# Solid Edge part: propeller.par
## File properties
Author: Georg
Template: Iso Metric Part.par
Last saved by: Georg
Revision: 7
Application: Solid Edge
Accuracy: 0,990
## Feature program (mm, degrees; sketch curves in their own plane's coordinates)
sketch for "unnamed RevolvedProtrusion 1" plane through (0, 0, 0) normal (1, 0, 0) x-axis (0, 1, 0)
  line (0, -121.0602) -> (-276.8667, -121.0602)
  line (0, -121.0602) -> (0, -271.0602)
revolve "unnamed RevolvedProtrusion 1" add finite 360 deg
lofted protrusion "unnamed LoftedProtrusion 1"
fillet "Round_1" radius 3.4154
pattern "unnamed Pattern 1" of "unnamed LoftedProtrusion 1"
lofted protrusion "unnamed LoftedProtrusion 2"
lofted protrusion "unnamed LoftedProtrusion 3"
sketch for "ExtrudedProtrusion_1" plane through (0, 0, -121.0602) normal (0, 1, 0) x-axis (-1, 0, 0)
  circle centre (0, 0) radius 15
extrude "ExtrudedProtrusion_1" add finite 170 along +normal
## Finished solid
Body 1: solid body, 29 faces, 93 edges, 68 vertices.
  Faces by surface: spline 12, plane 11, blend 4, cylinder 1, spun 1
  Edges by curve: intersection 40, circle 21, line 20, spline 12
Bounding box of the edges (mm; curved faces can reach further): 1087.408 x 276.360 x 941.723, from (-543.7038, -106.36, -441.7227) to (543.7038, 170, 500).
Cylindrical faces by radius (mm): R15 x1
Planar faces by outward normal: +y 2, +z 1, -z 2, oblique 6
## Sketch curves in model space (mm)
line (7.1074, -21.7531, 500) -> (11.6999, -26.3455, 500)
line (11.6999, -26.3455, 500) -> (-7.1074, -45.1528, 500)
line (-7.1074, -45.1528, 500) -> (-11.6999, -40.5604, 500)
line (-11.6999, -40.5604, 500) -> (7.1074, -21.7531, 500)
arc centre (65.8364, 27.9899, 250) radius 10 from (72.9075, 20.9188, 250) through (75.8322, 28.2807, 250) to (72.9075, 35.0609, 250)
line (72.9075, 35.0609, 250) -> (68.5138, 39.4546, 250)
arc centre (61.4428, 32.3835, 250) radius 10 from (68.5138, 39.4546, 250) through (61.1519, 42.3793, 250) to (54.3717, 39.4546, 250)
line (54.3717, 39.4546, 250) -> (-72.9075, -87.8246, 250)
arc centre (-65.8364, -94.8957, 250) radius 10 from (-72.9075, -87.8246, 250) through (-75.8322, -95.1865, 250) to (-72.9075, -101.9668, 250)
line (-72.9075, -101.9668, 250) -> (-68.5138, -106.3604, 250)
arc centre (-61.4428, -99.2894, 250) radius 10 from (-54.3717, -106.3604, 250) through (-61.7336, -109.2851, 250) to (-68.5138, -106.3604, 250)
line (-54.3717, -106.3604, 250) -> (72.9075, 20.9188, 250)
arc centre (78.034, -30.3461, 0) radius 10 from (78.034, -20.3461, 0) through (85.3077, -23.4837, 0) to (88.034, -30.3461, 0)
line (88.034, -30.3461, 0) -> (88.034, -36.5597, 0)
arc centre (78.034, -36.5597, 0) radius 10 from (88.034, -36.5597, 0) through (84.8964, -43.8334, 0) to (78.034, -46.5597, 0)
line (78.034, -46.5597, 0) -> (-78.034, -46.5597, 0)
arc centre (-78.034, -36.5597, 0) radius 10 from (-78.034, -46.5597, 0) through (-85.3077, -43.4221, 0) to (-88.034, -36.5597, 0)
line (-88.034, -36.5597, 0) -> (-88.034, -30.3461, 0)
arc centre (-78.034, -30.3461, 0) radius 10 from (-78.034, -20.3461, 0) through (-85.3077, -23.4837, 0) to (-88.034, -30.3461, 0)
line (-78.034, -20.3461, 0) -> (78.034, -20.3461, 0)
ellipse centre (0, 0, -121.0602) radii 276.8667, 150 from (0, -276.8667, -121.0602) through (0, -189.9974, -230.1662) to (0, 0, -271.0602)
line (0, 0, -121.0602) -> (0, -276.8667, -121.0602)
line (0, 0, -121.0602) -> (0, 0, -271.0602)
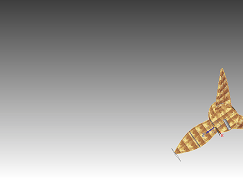
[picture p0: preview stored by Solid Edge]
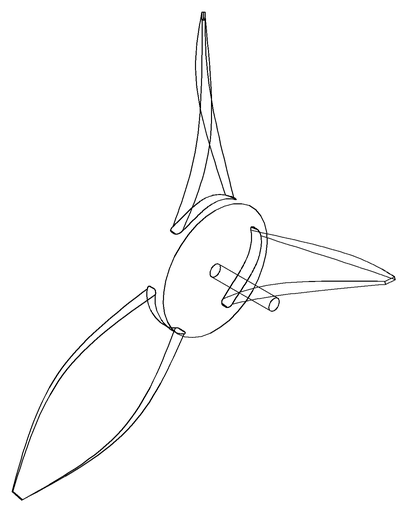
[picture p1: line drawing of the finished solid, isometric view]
